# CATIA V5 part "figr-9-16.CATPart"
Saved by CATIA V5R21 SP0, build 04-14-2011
Part number: Part1
Bounding box of the stored display mesh (mm): x -77.304 to 77.304, y -77.304 to 125.507, z 0 to 125
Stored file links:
  D:\CATIA V5R21 E-RESOURCES\CATIA-V5R21\catia-v5r21-prt\c09-catia-v5r20-prt\c09-catia-v5r21-figr-9-16.CATPart
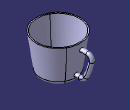
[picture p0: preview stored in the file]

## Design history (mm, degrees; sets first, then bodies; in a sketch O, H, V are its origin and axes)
Set1
  Plane1: type Normal, Curve Sketch3, RefPoint vertex of Sketch3
Body1 (main body)
  Sketch1 on yz-plane, origin (0, 0, 0), H (0, 1, 0), V (0, 0, 1)
    line L1 (0, 0) -> (60, 0)
    point P1 (60, 0)
    point P2 (60, 0)
    line L2 (60, 0) -> (77.5, 125)
    point P3 (77.5, 125)
    line L3 (77.5, 125) -> (0, 125)
    point P4 (0, 125)
    line L4 (0, 125) -> (0, 0)
    axis line L5 (0, 150.2858) -> (0, -31.0593)
    point P5 (0, 150.2858)
    "Radius" P1 L5 = 60
    "Radius" P3 L5 = 77.5
    distance L3 L1 = 125
    horizontal: L1 H, L3 H
    coincidence: P4 V, P2 P1, P5 V
    vertical: L4 V, L5 V
  Shaft1: profile Sketch1, axis Sketch1.L5, angle 360
  Fillet1: radius 15, on edge [face of Shaft1 | face of Shaft1]
  Shell1: ExtOffset 0, Face face of Shaft1, IntOffset 4
  Sketch2 on Plane1, origin (0, 62.9841, 0), H (-1, 0, 0), V (0, 0, 1)
    circle A1 centre (0, 22.002) radius 7.5
    reference projected point E1 (0, 22.002) from vertex of Sketch3
    radius A1 = 7.5
    concentricity: A1 E1
  Sketch3 on yz-plane, origin (0, 0, 0), H (0, 1, 0), V (0, 0, 1)
    line L1 (62.9841, 22.002) -> (78.2172, 22.002)
    arc A1 centre (78.2172, 44.1133) radius 22.1113 from (78.2172, 22.002) to (97.9307, 34.0988) ccw
    arc A2 centre (-112.3295, 140.9107) radius 235.8349 from (97.9307, 34.0988) to (117.8681, 89.6549) ccw
    arc A3 centre (104.0328, 92.7355) radius 14.1742 from (117.8681, 89.6549) to (104.4272, 106.9041) ccw
    arc A4 centre (93.6744, -279.4123) radius 386.4661 from (104.4272, 106.9041) to (82.9216, 106.9041) ccw
    horizontal: L1 H
    tangency: A1 L1, A2 A1, A3 A2, A4 A3
  Rib1: profile Sketch2, centre curve Sketch3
